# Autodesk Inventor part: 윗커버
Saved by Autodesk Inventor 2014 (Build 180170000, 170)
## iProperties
Created: 2026-03
Part Number: 윗커버
Material: 일반
Document SubType Name: Modeling
Designer: dg
Density: 1 g/cm^3
Appearance: 기본값
Author: dg
Author: jhkim
Creation Date: 2025-06-27
Sending System: Autodesk Inventor 2026
Preprocessor: ST-DEVELOPER v20.1
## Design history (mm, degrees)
node "윗커버1"
node "솔리드1"
node "기준1"
